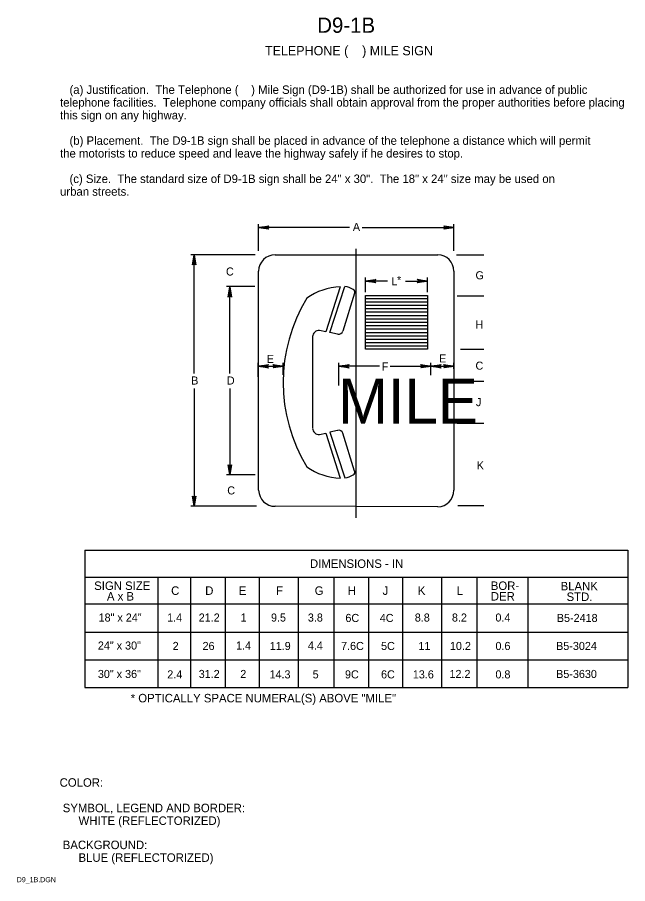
# Model space of a CAD drawing. Extents: x 0.013 to 0.192, y 0.004 to 0.259.
import ezdxf

# ---------------------------------------------------------------- set-up
doc = ezdxf.new("R2010")
doc.units = 0
for name, color, linetype in [('1', 7, 'Continuous'), ('2', 7, 'Continuous'), ('3', 7, 'Continuous')]:
    doc.layers.add(name, color=color, linetype=linetype)

# ---------------------------------------------------------------- blocks, each defined once
blk = doc.blocks.new('RARROW')
at = {"layer": '3'}
for p, q in [((-2.156, 0.28500000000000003), (-2.2665, 0.384625)), ((-2.2665, 0.384625), (0, 0)), ((0, 0), (-2.2665, -0.379125)), ((-2.156, 0.28500000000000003), (-2.075625, 0.12075)), ((0, 0), (-2.156, 0.28500000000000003)), ((-2.14975, -0.2705), (0, 0)), ((-2.075625, 0.12075), (0, 0)), ((0, 0), (-2.074, -0.108)), ((-2.2665, -0.379125), (-2.14975, -0.2705)), ((-2.074, -0.108), (-2.14975, -0.2705))]:
    blk.add_line(p, q, dxfattribs=at)

msp = doc.modelspace()

# ---------------------------------------------------------------- linework, layer by layer
at = {"layer": '3'}
for p, q in [((0.08375, 0.19037500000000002), (0.08375, 0.19825)), ((0.1105, 0.19725), (0.08375, 0.19725)), ((0.11425, 0.19725), (0.14125000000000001, 0.19725)), ((0.14125000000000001, 0.19037500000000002), (0.14125000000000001, 0.19825)), ((0.082375, 0.18925), (0.06375, 0.18925)), ((0.06475, 0.15425), (0.06475, 0.18925)), ((0.08275, 0.18925), (0.07425, 0.18925)), ((0.088625, 0.18925), (0.1365, 0.18925)), ((0.1125, 0.11175), (0.1125, 0.191)), ((0.14200000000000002, 0.18925), (0.150125, 0.18925)), ((0.08375, 0.11987500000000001), (0.08375, 0.184375)), ((0.14125000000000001, 0.184375), (0.14125000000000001, 0.11987500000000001)), ((0.11525, 0.17825), (0.11525, 0.1825)), ((0.12175, 0.1815), (0.11525, 0.1815)), ((0.127, 0.1815), (0.1335, 0.1815)), ((0.1335, 0.17825), (0.1335, 0.1825)), ((0.082625, 0.179875), (0.07425, 0.179875)), ((0.07525, 0.15425), (0.07525, 0.179875)), ((0.10775, 0.17975), (0.10350000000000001, 0.1665)), ((0.10475, 0.166375), (0.109125, 0.179875)), ((0.112, 0.177875), (0.1085, 0.16675)), ((0.11525, 0.176375), (0.1335, 0.176375)), ((0.14225000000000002, 0.177125), (0.150125, 0.177125)), ((0.11525, 0.175375), (0.1335, 0.175375)), ((0.11525, 0.174375), (0.1335, 0.174375)), ((0.11525, 0.173375), (0.1335, 0.173375)), ((0.11525, 0.172375), (0.1335, 0.172375)), ((0.11525, 0.171375), (0.1335, 0.171375)), ((0.11525, 0.170375), (0.1335, 0.170375)), ((0.11525, 0.169375), (0.1335, 0.169375)), ((0.10350000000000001, 0.1665), (0.10162500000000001, 0.166875)), ((0.107, 0.165875), (0.10475, 0.166375)), ((0.11525, 0.168375), (0.1335, 0.168375)), ((0.11525, 0.167375), (0.1335, 0.167375)), ((0.11525, 0.166375), (0.1335, 0.166375)), ((0.099625, 0.165125), (0.099625, 0.138125)), ((0.11525, 0.165375), (0.1335, 0.165375)), ((0.11525, 0.164375), (0.1335, 0.164375)), ((0.11525, 0.163375), (0.1335, 0.163375)), ((0.11525, 0.162375), (0.1335, 0.162375)), ((0.14325000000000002, 0.161375), (0.150125, 0.161375)), ((0.083625, 0.15325), (0.083625, 0.15737500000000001)), ((0.083625, 0.15637500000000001), (0.091, 0.15637500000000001)), ((0.085625, 0.15637500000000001), (0.083625, 0.15637500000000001)), ((0.088875, 0.15637500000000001), (0.091, 0.15637500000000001)), ((0.091, 0.153875), (0.091, 0.15737500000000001)), ((0.107375, 0.15075), (0.107375, 0.15737500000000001)), ((0.11937500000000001, 0.15637500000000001), (0.107375, 0.15637500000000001)), ((0.1225, 0.15637500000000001), (0.14125000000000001, 0.15637500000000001)), ((0.1345, 0.15375), (0.1345, 0.15737500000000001)), ((0.13625, 0.15637500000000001), (0.1345, 0.15637500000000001)), ((0.1395, 0.15637500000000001), (0.14125000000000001, 0.15637500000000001)), ((0.14125000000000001, 0.155625), (0.14125000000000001, 0.15737500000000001)), ((0.14225000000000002, 0.152), (0.150125, 0.152)), ((0.06475, 0.149875), (0.06475, 0.115125)), ((0.07525, 0.149875), (0.07525, 0.1245)), ((0.14225000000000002, 0.139625), (0.150125, 0.139625)), ((0.10162500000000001, 0.13625), (0.10350000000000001, 0.136625)), ((0.10350000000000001, 0.136625), (0.10775, 0.123375)), ((0.107, 0.1375), (0.10475, 0.137)), ((0.10475, 0.137), (0.109125, 0.1235)), ((0.112, 0.1255), (0.1085, 0.136625)), ((0.08275, 0.124375), (0.07425, 0.124375)), ((0.08275, 0.115125), (0.06375, 0.115125)), ((0.083125, 0.115125), (0.07425, 0.115125)), ((0.1365, 0.115), (0.088625, 0.115125)), ((0.142375, 0.115375), (0.150125, 0.115375)), ((0.03255266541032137, 0.1022469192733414), (0.19244733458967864, 0.1022469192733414)), ((0.03255266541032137, 0.1022469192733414), (0.03255266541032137, 0.06174691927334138)), ((0.19244733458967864, 0.1022469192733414), (0.19244733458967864, 0.06174691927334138)), ((0.19244733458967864, 0.09412191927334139), (0.032642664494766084, 0.09412191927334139)), ((0.05405576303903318, 0.09410552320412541), (0.05405576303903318, 0.06174691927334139)), ((0.06363821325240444, 0.09410552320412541), (0.06363821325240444, 0.06174691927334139)), ((0.07388821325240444, 0.09410552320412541), (0.07388821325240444, 0.06174691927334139)), ((0.08388821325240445, 0.09410552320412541), (0.08388821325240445, 0.06174691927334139)), ((0.09538821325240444, 0.09410552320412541), (0.09538821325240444, 0.06174691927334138)), ((0.10589000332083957, 0.0941219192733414), (0.10589000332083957, 0.06174691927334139)), ((0.11613821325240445, 0.09410552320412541), (0.11613821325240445, 0.06174691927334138)), ((0.12613821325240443, 0.09410552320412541), (0.12613821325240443, 0.06174691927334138)), ((0.13763821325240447, 0.09410552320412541), (0.13763821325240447, 0.06174691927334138)), ((0.14801321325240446, 0.09410552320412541), (0.14801321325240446, 0.06174691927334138)), ((0.16301321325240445, 0.09410552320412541), (0.16301321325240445, 0.06174691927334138)), ((0.032445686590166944, 0.0863719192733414), (0.19244733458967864, 0.0863719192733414)), ((0.03249722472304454, 0.07799691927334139), (0.19244733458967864, 0.07799691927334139)), ((0.032500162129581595, 0.0698719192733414), (0.19244733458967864, 0.0698719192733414)), ((0.032500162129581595, 0.06174691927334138), (0.19244733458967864, 0.06174691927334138))]:
    msp.add_line(p, q, dxfattribs=at)
msp.add_lwpolyline([(0.11525, 0.17725), (0.1335, 0.17725), (0.1335, 0.161375), (0.11525, 0.161375)], close=True, dxfattribs=at)
for centre, radius, start, end in [((0.08862500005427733, 0.18437499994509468), 0.004875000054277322, 90, 180), ((0.13643749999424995, 0.18443749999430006), 0.004812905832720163, 359.2559416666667, 89.25594166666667), ((0.10836168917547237, 0.1621784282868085), 0.017630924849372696, 91.92819722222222, 126.14840277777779), ((0.10822751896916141, 0.17338150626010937), 0.00655866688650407, 58.829263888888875, 81.7668888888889), ((0.11110462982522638, 0.17813766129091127), 0.001, 342.3777027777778, 58.82926388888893), ((0.10145876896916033, 0.16511162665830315), 0.0018049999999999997, 83.89159444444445, 180), ((0.1073384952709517, 0.16708638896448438), 0.00125, 256.66837777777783, 344.0920694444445), ((0.10145876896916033, 0.13808451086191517), 0.0018049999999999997, 180, 276.1084055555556), ((0.1073384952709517, 0.1362828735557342), 0.00125, 15.907930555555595, 103.33162222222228), ((0.10836168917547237, 0.1410177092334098), 0.0176309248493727, 233.85159722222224, 268.12181944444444), ((0.11110462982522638, 0.1252316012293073), 0.001, 301.1707361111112, 17.6222972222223), ((0.10822751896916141, 0.1299877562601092), 0.00655866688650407, 278.23311111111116, 301.1707361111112), ((0.08856249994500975, 0.119937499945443), 0.004812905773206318, 180.74406111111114, 270.74406111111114), ((0.13643750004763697, 0.11981249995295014), 0.004812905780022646, 270.74406111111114, 0.7440611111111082)]:
    msp.add_arc(centre, radius, start, end, dxfattribs=at)
msp.add_ellipse((0.13646066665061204, 0.15159906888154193), major_axis=(2.8508354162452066e-18, 0.04655767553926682), ratio=0.977334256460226, start_param=1.008604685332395, end_param=2.1329879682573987, dxfattribs=at)

# ---------------------------------------------------------------- block references
at = {"layer": '3', "xscale": 0.0013236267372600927, "yscale": 0.001309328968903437}
for p, rotation in [((0.08375, 0.19725), 180), ((0.06475, 0.18925), 90), ((0.11525, 0.1815), 180), ((0.07525, 0.17975), 90), ((0.083625, 0.15637500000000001), 180), ((0.107375, 0.15637500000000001), 180), ((0.1345, 0.15637500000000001), 180), ((0.07525, 0.124375), -90), ((0.06475, 0.115125), -90)]:
    msp.add_blockref('RARROW', p, dxfattribs=dict(at, rotation=rotation))
for p in [(0.14125000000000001, 0.19725), (0.1335, 0.1815), (0.091, 0.15637500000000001), (0.1345, 0.15637500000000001), (0.14125000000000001, 0.15637500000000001)]:
    msp.add_blockref('RARROW', p, dxfattribs=at)

# ---------------------------------------------------------------- texts
at = {"layer": '1'}
for s, height, p in [('D9-1B', 0.0045000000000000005, (0.101, 0.254625)), ('TELEPHONE (    ) MILE SIGN', 0.00275025, (0.085625, 0.248)), ('COLOR:', 0.0024997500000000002, (0.025125, 0.0325)), (' SYMBOL, LEGEND AND BORDER:', 0.0024997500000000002, (0.025125, 0.025)), ('      WHITE (REFLECTORIZED)', 0.0024997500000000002, (0.025125, 0.02125)), (' BACKGROUND:', 0.0024997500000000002, (0.025125, 0.014125)), ('      BLUE (REFLECTORIZED)', 0.0024997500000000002, (0.025125, 0.010375)), ('D9_1B.DGN', 0.0015, (0.0125, 0.004375))]:
    msp.add_text(s, height=height, dxfattribs=at).set_placement(p)
at = {"layer": '2'}
for s, p in [('   (a) Justification.  The Telephone (    ) Mile Sign (D9-1B) shall be authorized for use in advance of public', (0.02525, 0.23662525)), ('telephone facilities.  Telephone company officials shall obtain approval from the proper authorities before placing', (0.02525, 0.23287549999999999)), ('this sign on any highway.', (0.02525, 0.22912575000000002)), ('   (b) Placement.  The D9-1B sign shall be placed in advance of the telephone a distance which will permit', (0.02525, 0.22162625)), ('the motorists to reduce speed and leave the highway safely if he desires to stop.', (0.02525, 0.2178765)), ('   (c) Size.  The standard size of D9-1B sign shall be 24" x 30".  The 18" x 24" size may be used on ', (0.02525, 0.210377)), ('urban streets.', (0.02525, 0.20662725))]:
    msp.add_text(s, height=0.0024997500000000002, dxfattribs=at).set_placement(p)
at = {"layer": '3'}
for s, height, p in [('A', 0.0023752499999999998, (0.1115, 0.19625)), ('C', 0.0023752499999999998, (0.074125, 0.183125)), ('G', 0.0023752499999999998, (0.147625, 0.182)), ('L ', 0.0023752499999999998, (0.122875, 0.18025)), ('*', 0.0023752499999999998, (0.1245, 0.180625)), ('H', 0.0023752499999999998, (0.147625, 0.1675)), ('E', 0.0023752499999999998, (0.08612500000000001, 0.15737500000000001)), ('E', 0.0023752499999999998, (0.136875, 0.1575)), ('F', 0.0023752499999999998, (0.12, 0.155125)), ('C', 0.0023752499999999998, (0.147625, 0.155375)), ('B', 0.0023752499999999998, (0.063875, 0.151)), ('D', 0.0023752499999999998, (0.074375, 0.151)), ('MILE', 0.013198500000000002, (0.107125, 0.1395)), ('J', 0.0023752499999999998, (0.14775, 0.144625)), ('K', 0.0023752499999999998, (0.148, 0.126)), ('C', 0.0023752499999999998, (0.0745, 0.11862500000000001)), ('DIMENSIONS - IN', 0.0024997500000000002, (0.09886310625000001, 0.09698052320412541)), ('SIGN SIZE', 0.0024997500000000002, (0.03530576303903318, 0.0904805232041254)), ('BOR-', 0.0024997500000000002, (0.15213821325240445, 0.0904805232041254)), ('BLANK', 0.0024997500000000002, (0.17270033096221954, 0.0903555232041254)), ('A x B', 0.0024997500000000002, (0.03905576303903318, 0.0873555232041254)), ('C', 0.0024997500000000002, (0.05797198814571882, 0.08902801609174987)), ('D', 0.0024997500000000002, (0.06801321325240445, 0.08902801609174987)), ('E', 0.0024997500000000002, (0.07788821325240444, 0.08902801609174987)), ('F', 0.0024997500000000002, (0.08888821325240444, 0.08902801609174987)), ('G', 0.0024997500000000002, (0.10026321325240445, 0.08902801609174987)), ('H', 0.0024997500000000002, (0.11001321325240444, 0.08902801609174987)), ('J', 0.0024997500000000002, (0.12026321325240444, 0.08902801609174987)), ('K', 0.0024997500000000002, (0.13063821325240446, 0.08902801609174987)), ('L', 0.0024997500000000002, (0.14205875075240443, 0.08902801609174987)), ('DER', 0.0024997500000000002, (0.15213821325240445, 0.0873555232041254)), ('STD.', 0.0024997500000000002, (0.17445033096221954, 0.0872305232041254)), ('18" x 24"', 0.0023752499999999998, (0.03660570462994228, 0.08116789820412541)), ('1.4', 0.0023752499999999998, (0.05679491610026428, 0.08116789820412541)), ('21.2', 0.0023752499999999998, (0.06608841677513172, 0.08116789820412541)), ('1', 0.0023752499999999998, (0.07840716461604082, 0.08116789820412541)), ('9.5', 0.0023752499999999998, (0.08738460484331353, 0.08116789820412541)), ('3.8', 0.0023752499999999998, (0.09824376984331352, 0.08116789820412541)), ('6C', 0.0023752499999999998, (0.109302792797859, 0.08104289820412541)), ('4C', 0.0023752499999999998, (0.119427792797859, 0.08104289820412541)), ('8.8', 0.0023752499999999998, (0.12974376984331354, 0.08116789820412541)), ('8.2', 0.0023752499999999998, (0.14068318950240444, 0.08116789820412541)), ('0.4', 0.0023752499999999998, (0.1534952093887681, 0.08116789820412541)), ('B5-2418', 0.0023752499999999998, (0.17158205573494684, 0.08104289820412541)), ('24" x 30"', 0.0023752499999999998, (0.03638977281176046, 0.0729178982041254)), ('2', 0.0023752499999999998, (0.058420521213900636, 0.0727928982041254)), ('26', 0.0023752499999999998, (0.06722457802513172, 0.0727928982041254)), ('1.4', 0.0023752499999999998, (0.0770861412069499, 0.0729178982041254)), ('11.9', 0.0023752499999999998, (0.08700648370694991, 0.0727928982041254)), ('4.4', 0.0023752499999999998, (0.09824520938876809, 0.0729178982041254)), ('7.6C', 0.0023752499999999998, (0.10802423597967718, 0.0727928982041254)), ('5C', 0.0023752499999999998, (0.119802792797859, 0.0727928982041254)), ('11', 0.0023752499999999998, (0.13081239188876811, 0.0727928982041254)), ('10.2', 0.0023752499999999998, (0.1400884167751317, 0.0727928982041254)), ('0.6', 0.0023752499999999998, (0.15350672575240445, 0.0727928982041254)), ('B5-3024', 0.0023752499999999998, (0.17136756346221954, 0.0727928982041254)), ('30" x 36"', 0.0023752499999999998, (0.03638977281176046, 0.06454289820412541)), ('2.4', 0.0023752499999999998, (0.056828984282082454, 0.06441789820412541)), ('31.2', 0.0023752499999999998, (0.06608841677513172, 0.06454289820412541)), ('2', 0.0023752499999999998, (0.07833674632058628, 0.06454289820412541)), ('14.3', 0.0023752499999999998, (0.08694650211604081, 0.06441789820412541)), ('5', 0.0023752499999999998, (0.09966316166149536, 0.06441789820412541)), ('9C', 0.0023752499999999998, (0.109177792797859, 0.06441789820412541)), ('6C', 0.0023752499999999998, (0.119802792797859, 0.06441789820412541)), ('13.6', 0.0023752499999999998, (0.1291619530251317, 0.06441789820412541)), ('12.2', 0.0023752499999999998, (0.1399634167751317, 0.06454289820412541)), ('0.8', 0.0023752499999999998, (0.15349376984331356, 0.06441789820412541)), ('B5-3630', 0.0023752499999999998, (0.17137404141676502, 0.06454289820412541)), ('* OPTICALLY SPACE NUMERAL(S) ABOVE "MILE"', 0.0024997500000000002, (0.04605576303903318, 0.0573555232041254))]:
    msp.add_text(s, height=height, dxfattribs=at).set_placement(p)

doc.saveas('drawing.dxf')
